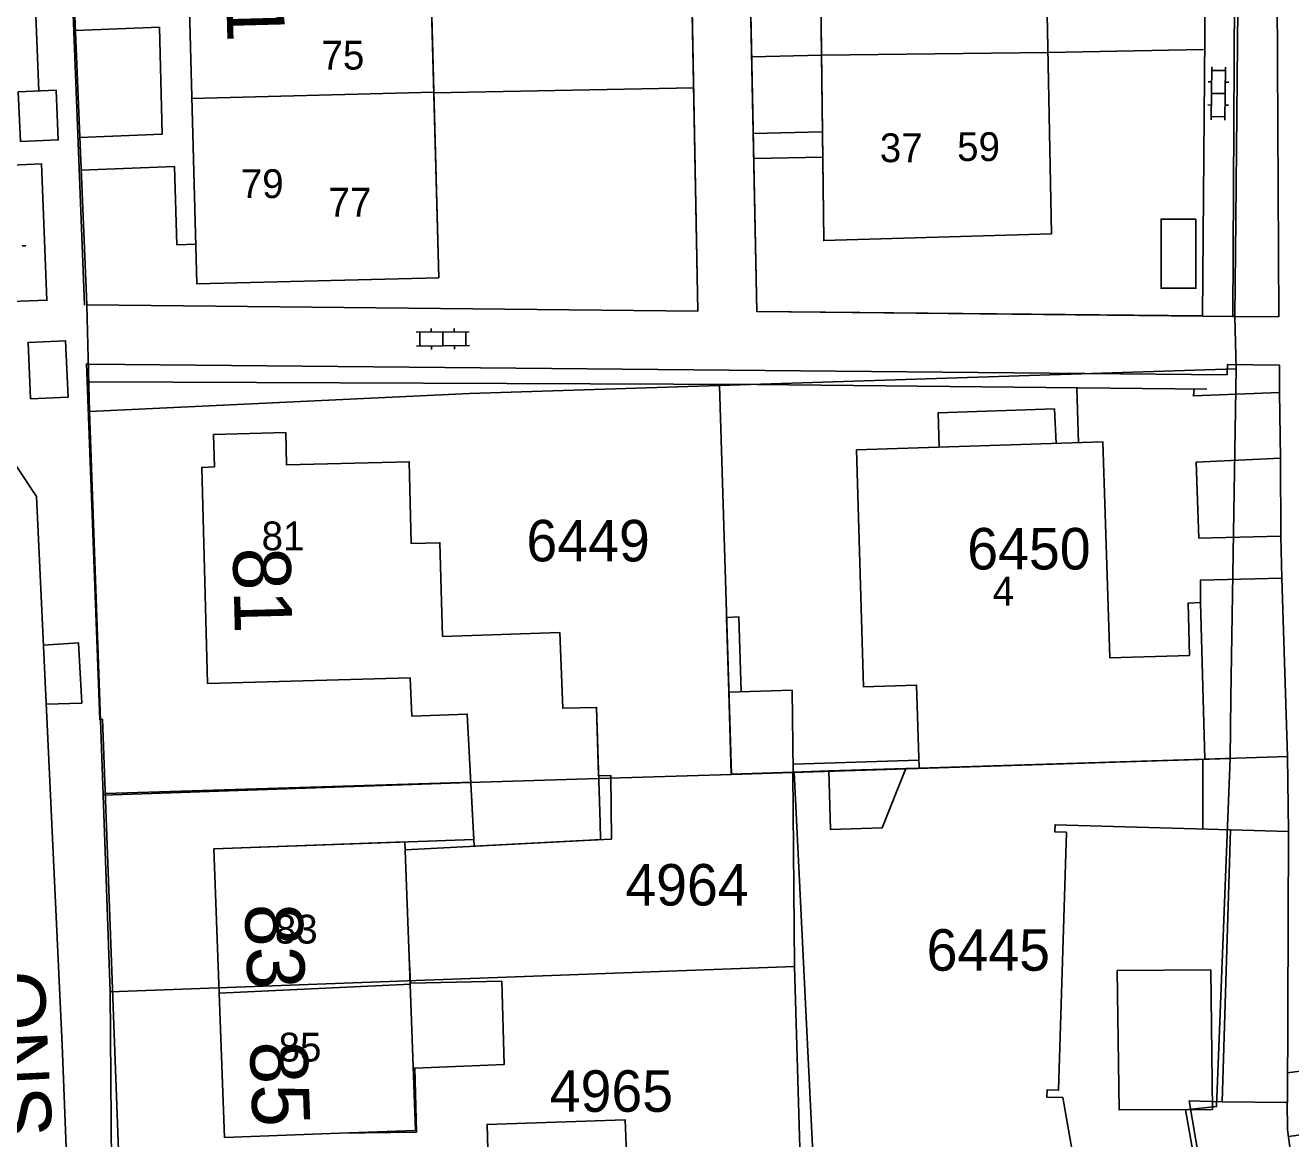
# Model space of a CAD drawing. Extents: x 148816 to 151297, y 399515 to 402500.
# Drawn here: x 150275.9 to 150330.8, y 399886 to 399934.3 of the extents above; entities that cross this region are included whole.
import ezdxf

# ---------------------------------------------------------------- set-up
doc = ezdxf.new("R2010")
doc.units = 0
for name, color, linetype in [('B01 Hoofdgebouw  [D] Norm', 7, 'Continuous'), ('B01 Hoofdgebouw  [T] Norm', 7, 'Continuous'), ('B01 Hoofdgebouw secundair [T] Norm', 7, 'Continuous'), ('B01 hoofgebouw', 7, 'Continuous'), ('B02 Bijgebouw  [D] Norm', 7, 'Continuous'), ('B02 Bijgebouw  [T] Norm', 7, 'Continuous'), ('B07 Tussenmuur  [D] Norm', 7, 'Continuous'), ('G01 perceelsgrens', 7, 'Continuous'), ('S02 Open verharding  Norm', 7, 'Continuous'), ('T01 Muur  [T] Norm', 7, 'Continuous'), ('T03 Hek raster  [T] Norm', 7, 'Continuous'), ('T04 Haag heg  [D] Gem', 7, 'Continuous'), ('V00 Kant verharding algemeen  [T] Norm', 7, 'Continuous'), ('V00 Kant verharding algemeen secundair  [T] Gem', 7, 'Continuous'), ('V00 Kant verharding algemeen secundair  [T] Norm', 7, 'Continuous'), ('V06 Kant onverhard  [T] Gem', 7, 'Continuous'), ('Z01 perceelnummer', 7, 'Continuous'), ('Z02 huisnummer', 7, 'Continuous'), ('Z02 Huisnummer  [Tekst] Norm', 7, 'Continuous'), ('Z06 straatnaam', 7, 'Continuous')]:
    doc.layers.add(name, color=color, linetype=linetype)

msp = doc.modelspace()

# ---------------------------------------------------------------- linework, layer by layer
at = {"layer": 'B01 Hoofdgebouw  [D] Norm'}
for points in [[(150300.799, 399901.718), (150301.328, 399901.742), (150301.353, 399898.978), (150301.042, 399898.964)], [(150292.58, 399893.86), (150292.633, 399892.73), (150296.597, 399892.816), (150296.706, 399889.204), (150292.818, 399889.043), (150292.896, 399886.258)], [(150292.896, 399886.258), (150289.555, 399886.215)]]:
    msp.add_lwpolyline(points, dxfattribs=at)
at = {"layer": 'B01 Hoofdgebouw  [T] Norm'}
for p, q in [((150292.98, 399956.34), (150293.86, 399923.33)), ((150283.37, 399923.06), (150282.48, 399956.06)), ((150310.57, 399924.94), (150310.18, 399956.08)), ((150319.88, 399953.85), (150320.45, 399925.24)), ((150320.45, 399925.24), (150310.57, 399924.94)), ((150293.86, 399923.33), (150283.37, 399923.06)), ((150284.09, 399916.53), (150287.23, 399916.61)), ((150287.23, 399916.61), (150287.26, 399915.21)), ((150284.13, 399915.12), (150284.09, 399916.53)), ((150283.58, 399915.1), (150284.13, 399915.12)), ((150283.83, 399905.72), (150283.58, 399915.1)), ((150287.26, 399915.21), (150292.58, 399915.35)), ((150292.58, 399915.35), (150292.67, 399911.8)), ((150292.67, 399911.8), (150293.91, 399911.83)), ((150293.91, 399911.83), (150294.03, 399907.77)), ((150294.03, 399907.77), (150299.11, 399907.94)), ((150299.11, 399907.94), (150299.24, 399904.65)), ((150292.62, 399905.97), (150283.83, 399905.72)), ((150292.7, 399904.31), (150292.62, 399905.97)), ((150299.24, 399904.65), (150300.71, 399904.69)), ((150300.71, 399904.69), (150300.799, 399901.718)), ((150295.1, 399904.4), (150292.7, 399904.31)), ((150295.385, 399898.965), (150295.1, 399904.4)), ((150295.385, 399898.965), (150284.1, 399898.55)), ((150284.1, 399898.55), (150284.56, 399886.03)), ((150292.58, 399893.86), (150292.395, 399898.855)), ((150292.408, 399898.514), (150301.042, 399898.964)), ((150284.56, 399886.03), (150289.555, 399886.215))]:
    msp.add_line(p, q, dxfattribs=at)
for points in [[(150314.707, 399902.059), (150314.597, 399905.657), (150312.288, 399905.587), (150311.989, 399915.858), (150322.683, 399916.208), (150322.986, 399906.837), (150326.434, 399906.948), (150326.377, 399909.216), (150326.919, 399909.24), (150327.101, 399902.438), (150314.707, 399902.059)], [(150314.345, 399877.954), (150323.202, 399879.551), (150322.731, 399882.544), (150321.891, 399882.317), (150320.94, 399887.766), (150320.251, 399887.786), (150320.26, 399888.096), (150320.759, 399888.081), (150321.099, 399899.276), (150320.599, 399899.291), (150320.608, 399899.601), (150328.212, 399899.382), (150327.855, 399887.583), (150326.426, 399887.626), (150326.989, 399884.303), (150327.957, 399884.44), (150329.17, 399876.992), (150328.42, 399876.87), (150329.153, 399872.591), (150329.477, 399872.676)]]:
    msp.add_lwpolyline(points, dxfattribs=at)
at = {"layer": 'B01 Hoofdgebouw secundair [T] Norm'}
msp.add_lwpolyline([(150315.58, 399915.976), (150315.53, 399917.472), (150320.577, 399917.639), (150320.649, 399916.141)], dxfattribs=at)
at = {"layer": 'B01 hoofgebouw'}
for points in [[(150324.71, 399962.705), (150319.757, 399962.615), (150319.393, 399982.746), (150325.847, 399982.863), (150325.814, 399984.724), (150319.354, 399984.607), (150319.206, 399992.77), (150289.82, 399991.79), (150284.82, 399991.7), (150284.97, 399983.64), (150298.59, 399984.03), (150298.62, 399982.78), (150298.51, 399982.77), (150298.5, 399982.34), (150309.46, 399982.65), (150309.94, 399959.81), (150309.73, 399959.81), (150309.97, 399956.06), (150310.18, 399956.08), (150310.57, 399924.94), (150320.45, 399925.24), (150319.88, 399953.85), (150324.88, 399953.95), (150324.71, 399962.705)], [(150292.98, 399956.34), (150282.48, 399956.06), (150283.37, 399923.06), (150293.86, 399923.33), (150292.98, 399956.34)], [(150300.393, 399898.931), (150295.4, 399898.67), (150295.1, 399904.4), (150292.7, 399904.31), (150292.62, 399905.97), (150283.83, 399905.72), (150283.58, 399915.1), (150284.13, 399915.12), (150284.09, 399916.53), (150287.23, 399916.61), (150287.26, 399915.21), (150292.58, 399915.35), (150292.67, 399911.8), (150293.91, 399911.83), (150294.03, 399907.77), (150299.11, 399907.94), (150299.24, 399904.65), (150300.71, 399904.69), (150300.86, 399899.69)], [(150300.86, 399899.69), (150300.882, 399898.956)], [(150292.578, 399893.858), (150292.395, 399898.854), (150284.1, 399898.55), (150284.56, 399886.03), (150289.557, 399886.213)], [(150300.393, 399898.931), (150300.882, 399898.956)], [(150292.578, 399893.858), (150292.854, 399886.334), (150289.557, 399886.213)], [(150327.37, 399893.3), (150323.3, 399893.28), (150323.39, 399887.23), (150327.44, 399887.25), (150327.37, 399893.3)]]:
    msp.add_lwpolyline(points, dxfattribs=at)
at = {"layer": 'B02 Bijgebouw  [D] Norm'}
for points in [[(150326.715, 399925.871), (150325.204, 399925.871), (150325.204, 399922.877), (150326.715, 399922.877)], [(150310.789, 399901.939), (150314.127, 399902.041), (150313.102, 399899.459), (150310.867, 399899.39)]]:
    msp.add_lwpolyline(points, close=True, dxfattribs=at)
msp.add_lwpolyline([(150296.139, 399880.03), (150295.961, 399886.598), (150301.954, 399886.797), (150302.081, 399883.514), (150303.997, 399883.588)], dxfattribs=at)
at = {"layer": 'B02 Bijgebouw  [T] Norm'}
msp.add_lwpolyline([(150309.244, 399901.882), (150309.191, 399905.432), (150306.447, 399905.348), (150306.556, 399901.8)], close=True, dxfattribs=at)
at = {"layer": 'B07 Tussenmuur  [D] Norm'}
for p, q in [((150310.469, 399932.983), (150320.299, 399933.106)), ((150310.469, 399932.983), (150320.299, 399933.106)), ((150283.153, 399931.099), (150293.645, 399931.382)), ((150283.153, 399931.099), (150293.645, 399931.382)), ((150292.635, 399892.68), (150284.33, 399892.29)), ((150292.635, 399892.68), (150284.33, 399892.29))]:
    msp.add_line(p, q, dxfattribs=at)
at = {"layer": 'G01 perceelsgrens'}
for points in [[(150328.408, 399921.647), (150307.67, 399921.86), (150306.46, 399980.24), (150277.03, 399979.43), (150275.992, 399991.677)], [(150278.59, 399922.15), (150305.11, 399921.88), (150304.45, 399956.58), (150292.98, 399956.34), (150282.48, 399956.06), (150277.19, 399955.92)], [(150278.59, 399922.15), (150277.754, 399942.325), (150277.19, 399955.92)], [(150328.609, 399942.636), (150328.451, 399925.862), (150328.408, 399921.647)], [(150278.702, 399917.523), (150278.59, 399922.15)], [(150328.408, 399921.647), (150328.458, 399919.374)], [(150328.458, 399919.374), (150306.046, 399918.656)], [(150328.458, 399919.374), (150328.236, 399905.121), (150328.208, 399902.474)], [(150306.046, 399918.656), (150295.198, 399918.309), (150278.702, 399917.523)], [(150306.046, 399918.656), (150306.559, 399901.783)], [(150279.306, 399900.885), (150278.702, 399917.523)], [(150328.208, 399902.474), (150309.219, 399901.866)], [(150328.208, 399902.474), (150327.612, 399887.369), (150326.261, 399887.225), (150328.878, 399872.513)], [(150306.559, 399901.783), (150300.796, 399901.603), (150295.213, 399901.428), (150279.306, 399900.885)], [(150309.219, 399901.866), (150306.559, 399901.783)], [(150309.219, 399901.866), (150309.298, 399893.451)], [(150279.607, 399892.352), (150279.306, 399900.885)], [(150309.298, 399893.451), (150279.607, 399892.352)], [(150309.298, 399893.451), (150309.523, 399885.582), (150308.856, 399885.453), (150309.125, 399883.867)], [(150279.68, 399882.949), (150279.607, 399892.352)]]:
    msp.add_lwpolyline(points, dxfattribs=at)
at = {"layer": 'S02 Open verharding  Norm'}
for p, q in [((150327.401, 399932.472), (150327.375, 399930.173)), ((150327.4, 399932.322), (150328, 399932.315)), ((150328.001, 399932.465), (150327.975, 399930.166)), ((150327.394, 399931.822), (150327.244, 399931.824)), ((150328.144, 399931.814), (150327.994, 399931.815)), ((150327.988, 399931.316), (150327.388, 399931.322)), ((150327.382, 399930.823), (150327.232, 399930.824)), ((150327.376, 399930.323), (150327.976, 399930.316)), ((150328.132, 399930.814), (150327.982, 399930.816)), ((150275.79, 399924.711), (150275.94, 399924.714)), ((150295.187, 399920.986), (150292.887, 399920.968)), ((150293.037, 399920.969), (150293.041, 399920.369)), ((150293.537, 399920.973), (150293.535, 399921.123)), ((150294.041, 399920.377), (150294.037, 399920.977)), ((150294.537, 399920.981), (150294.535, 399921.131)), ((150295.037, 399920.985), (150295.041, 399920.385)), ((150295.191, 399920.386), (150292.891, 399920.368)), ((150293.543, 399920.223), (150293.541, 399920.373)), ((150294.543, 399920.231), (150294.541, 399920.381))]:
    msp.add_line(p, q, dxfattribs=at)
at = {"layer": 'T01 Muur  [T] Norm'}
for p, q in [((150314.696, 399902.399), (150309.239, 399902.232)), ((150310.789, 399901.939), (150309.244, 399901.882)), ((150314.127, 399902.041), (150314.707, 399902.059))]:
    msp.add_line(p, q, dxfattribs=at)
msp.add_lwpolyline([(150306.982, 399905.364), (150306.888, 399908.613), (150306.348, 399908.597), (150306.447, 399905.348)], dxfattribs=at)
at = {"layer": 'T03 Hek raster  [T] Norm'}
for points in [[(150327.195, 399918.5), (150307.671, 399918.703)], [(150321.627, 399916.17), (150321.556, 399918.559)], [(150327.015, 399902.435), (150327.014, 399899.417)]]:
    msp.add_lwpolyline(points, dxfattribs=at)
at = {"layer": 'T04 Haag heg  [D] Gem'}
for p, q in [((150320.299, 399933.106), (150327.043, 399933.228)), ((150307.441, 399932.92), (150310.469, 399932.983)), ((150304.926, 399931.57), (150293.646, 399931.356)), ((150307.671, 399918.703), (150278.729, 399918.816))]:
    msp.add_line(p, q, dxfattribs=at)
for points in [[(150309.723, 399885.069), (150310.105, 399885.047), (150309.285, 399901.883)], [(150295.327, 399901.452), (150279.397, 399900.955)]]:
    msp.add_lwpolyline(points, dxfattribs=at)
at = {"layer": 'V00 Kant verharding algemeen  [T] Norm'}
for p, q in [((150306.46, 399980.24), (150307.67, 399921.86)), ((150304.45, 399956.58), (150305.11, 399921.88)), ((150328.45, 399947.22), (150328.32, 399921.65)), ((150330.2, 399943.95), (150330.32, 399921.63)), ((150327, 399921.67), (150327.151, 399938.756)), ((150278.096, 399934.055), (150281.741, 399934.206)), ((150281.741, 399934.206), (150281.867, 399929.56)), ((150278.289, 399929.412), (150281.867, 399929.56)), ((150307.51, 399929.59), (150310.511, 399929.652)), ((150278.348, 399927.994), (150282.399, 399928.162)), ((150282.399, 399928.162), (150282.491, 399924.759)), ((150307.532, 399928.496), (150310.525, 399928.558)), ((150283.324, 399924.781), (150282.491, 399924.759)), ((150305.11, 399921.88), (150278.59, 399922.15)), ((150307.67, 399921.86), (150327, 399921.67)), ((150328.32, 399921.65), (150330.32, 399921.63)), ((150328.07, 399919.12), (150278.7, 399919.58)), ((150328.09, 399919.57), (150328.07, 399919.12))]:
    msp.add_line(p, q, dxfattribs=at)
for points in [[(150279.875, 399829.592), (150277.518, 399890.054), (150276.415, 399913.833), (150274.799, 399916.237), (150272.927, 399964.275), (150272.256, 399979.477)], [(150278.498, 399922.134), (150277.176, 399955.904)], [(150275.618, 399931.398), (150275.711, 399929.241), (150277.354, 399929.311), (150277.261, 399931.469), (150275.618, 399931.398)], [(150277.782, 399918.15), (150276.152, 399918.077), (150276.041, 399920.525), (150277.672, 399920.599), (150277.782, 399918.15)], [(150281.834, 399827.705), (150281.023, 399849.422), (150281.264, 399850.384), (150279.268, 399904.177), (150279.152, 399904.151), (150278.584, 399919.605)], [(150330.348, 399918.357), (150330.35, 399919.53), (150328.09, 399919.57)], [(150326.643, 399918.503), (150326.608, 399918.201), (150330.348, 399918.357)], [(150326.845, 399912.03), (150330.4, 399912.125), (150330.388, 399915.5), (150326.728, 399915.331), (150326.845, 399912.03)], [(150327.101, 399902.438), (150330.685, 399902.558), (150330.443, 399910.302), (150326.912, 399910.212), (150326.919, 399909.24)], [(150276.823, 399904.828), (150278.375, 399904.877), (150278.231, 399907.485), (150276.703, 399907.385)], [(150330.683, 399887.547), (150330.727, 399899.299), (150328.212, 399899.382)], [(150330.682, 399887.555), (150327.855, 399887.583)]]:
    msp.add_lwpolyline(points, dxfattribs=at)
at = {"layer": 'V00 Kant verharding algemeen secundair  [T] Gem'}
for points in [[(150330.689, 399888.831), (150335.643, 399889.505)], [(150330.727, 399886.081), (150336.012, 399886.8)]]:
    msp.add_lwpolyline(points, dxfattribs=at)
at = {"layer": 'V00 Kant verharding algemeen secundair  [T] Norm'}
for p, q in [((150330.348, 399918.357), (150330.388, 399915.5)), ((150330.4, 399912.125), (150330.443, 399910.302)), ((150330.685, 399902.558), (150330.727, 399899.299))]:
    msp.add_line(p, q, dxfattribs=at)
msp.add_lwpolyline([(150332.514, 399873.033), (150330.688, 399886.368), (150330.68, 399887.546)], dxfattribs=at)
at = {"layer": 'V06 Kant onverhard  [T] Gem'}
for points in [[(150276.506, 399931.436), (150276.127, 399940.916)], [(150274.564, 399922.277), (150276.86, 399922.355), (150276.627, 399928.265), (150274.334, 399928.172)]]:
    msp.add_lwpolyline(points, dxfattribs=at)

# ---------------------------------------------------------------- texts
at = {"layer": 'Z01 perceelnummer'}
for s, p in [('6449', (150297.666, 399911.024)), ('6450', (150316.793, 399910.673)), ('4964', (150301.956, 399896.094)), ('6445', (150315.031, 399893.267)), ('4965', (150298.676, 399887.147))]:
    msp.add_text(s, height=1.8, dxfattribs=at).set_placement(p)
at = {"layer": 'Z02 huisnummer'}
for s, rotation, p in [('77 t/m 61', 271.5466, (150284.317, 399947.462)), ('81', 271.4894, (150284.922, 399911.601)), ('83', 272.1211, (150285.439, 399896.141)), ('85', 272.1211, (150285.658, 399890.173))]:
    msp.add_text(s, height=2.5, rotation=rotation, dxfattribs=at).set_placement(p)
at = {"layer": 'Z02 Huisnummer  [Tekst] Norm'}
for s, p in [('75', (150288.774, 399932.361)), ('37', (150313, 399928.343)), ('59', (150316.355, 399928.392)), ('79', (150285.272, 399926.785)), ('77', (150289.077, 399925.982)), ('81', (150286.175, 399911.505)), ('4', (150317.898, 399909.109)), ('83', (150286.748, 399894.445)), ('85', (150286.91, 399889.327))]:
    msp.add_text(s, height=1.25, dxfattribs=at).set_placement(p)
at = {"layer": 'Z06 straatnaam'}
msp.add_text('ONS DOELSTRAAT', height=2.5, rotation=272.8081, dxfattribs=at).set_placement((150274.243, 399893.198))

doc.saveas('drawing.dxf')
